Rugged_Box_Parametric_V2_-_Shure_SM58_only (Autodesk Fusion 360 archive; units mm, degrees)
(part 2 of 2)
sketch "Sketch1" plane through (0, 0, 0) normal (0, -1, 0) x axis (1, 0, 0)
  line L1 (27, -83.5799) -> (13, -83.5799)
  line L2 (30.5799, -64) -> (30.5799, -80)
  line L3 (33.2103, -64) -> (30.5799, -64)
  line L4 (33.2103, -62.8) -> (33.2103, -64)
  line L5 (30.5799, -62.8) -> (33.2103, -62.8)
  line L6 (30.5799, -32.2) -> (30.5799, -62.8)
  line L7 (33.2103, -32.2) -> (30.5799, -32.2)
  line L8 (33.2103, -31) -> (33.2103, -32.2)
  line L9 (30.5799, -31) -> (33.2103, -31)
  line L10 (30.5799, 31) -> (30.5799, -31)
  line L11 (33.2103, 31) -> (30.5799, 31)
  line L12 (33.2103, 32.2) -> (33.2103, 31)
  line L13 (30.5799, 32.2) -> (33.2103, 32.2)
  line L14 (30.5799, 62.8) -> (30.5799, 32.2)
  line L15 (33.2103, 62.8) -> (30.5799, 62.8)
  line L16 (33.2103, 64) -> (33.2103, 62.8)
  line L17 (30.5799, 64) -> (33.2103, 64)
  line L18 (30.5799, 80) -> (30.5799, 64)
  line L19 (13, 83.5799) -> (27, 83.5799)
  line L20 (13, 86.2103) -> (13, 83.5799)
  line L21 (10, 86.2103) -> (13, 86.2103)
  line L22 (10, 83.5799) -> (10, 86.2103)
  line L23 (-10, 83.5799) -> (10, 83.5799)
  line L24 (-10, 86.2103) -> (-10, 83.5799)
  line L25 (-13, 86.2103) -> (-10, 86.2103)
  line L26 (-13, 83.5799) -> (-13, 86.2103)
  line L27 (-27, 83.5799) -> (-13, 83.5799)
  line L28 (-30.5799, 48.1) -> (-30.5799, 80)
  line L29 (-33.2103, 48.1) -> (-30.5799, 48.1)
  line L30 (-33.2103, 46.9) -> (-33.2103, 48.1)
  line L31 (-30.5799, 46.9) -> (-33.2103, 46.9)
  line L32 (-30.5799, -46.9) -> (-30.5799, 46.9)
  line L33 (-33.2103, -46.9) -> (-30.5799, -46.9)
  line L34 (-33.2103, -48.1) -> (-33.2103, -46.9)
  line L35 (-30.5799, -48.1) -> (-33.2103, -48.1)
  line L36 (-30.5799, -80) -> (-30.5799, -48.1)
  line L37 (-13, -83.5799) -> (-27, -83.5799)
  line L38 (-13, -86.2103) -> (-13, -83.5799)
  line L39 (-10, -86.2103) -> (-13, -86.2103)
  line L40 (-10, -83.5799) -> (-10, -86.2103)
  line L41 (10, -83.5799) -> (-10, -83.5799)
  line L42 (10, -86.2103) -> (10, -83.5799)
  line L43 (13, -86.2103) -> (10, -86.2103)
  line L44 (13, -83.5799) -> (13, -86.2103)
  curve K1
  curve K2
  curve K3
  curve K4
  curve K5
  curve K6
  curve K7
  curve K8
  line L45 (-21.211, -1.1301) -> (-5.3045, -3.1151)
  curve K9 (-19.3176, 40.6782) -> (-15.6607, 42.0595)
  curve K10 (2.8159, -3.752) -> (1.8168, -8.457)
  line L46 (-16.007, 15.7968) -> (-21.211, 16.4496)
  curve K11 (-9.0516, -67.3301) -> (-19.8563, -68.0148)
  line L47 (1.8234, 23.3639) -> (1.8234, 13.6154)
  line L48 (-21.211, 16.4496) -> (-21.211, 36.7321)
  line L49 (1.8247, -33.0691) -> (1.8247, -44.2373)
  line L50 (-13.1967, 31.4711) -> (-16.007, 31.8545)
  curve K12 (-9.8039, -47.4736) -> (-9.1657, -46.5952)
  line L51 (-10.21, -13.8959) -> (-21.211, -12.5106)
  line L52 (-19.8563, -68.0015) -> (-19.8656, -67.9511)
  line L53 (-5.3045, -3.1151) -> (-5.3045, -0.107)
  curve K13 (-4.1276, -13.7313) -> (-10.21, -13.8959)
  line L54 (-21.211, 13.3965) -> (-9.7695, 12.0033)
  line L55 (-13.2392, -31.1969) -> (-13.2392, -27.7444)
  line L56 (-5.3045, -0.107) -> (-21.211, 1.8488)
  line L57 (1.8287, 67.7994) -> (1.8287, 43.0268)
  line L58 (-21.2123, -15.581) -> (1.8247, -18.4099)
  line L59 (2.8159, -2.6905) -> (2.8159, -3.752)
  line L60 (1.8168, -8.457) -> (1.5925, -8.8697)
  curve K14 (-19.8656, -67.9511) -> (-21.215, -64.0793)
  line L61 (-4.0294, 43.7313) -> (-21.2163, 45.8424)
  line L62 (-21.211, 13.3965) -> (-21.211, 1.8488)
  line L63 (-21.211, -12.5106) -> (-21.211, -1.1301)
  line L64 (-6.2506, -28.64) -> (-6.2506, -32.0779)
  curve K15 (-21.211, 36.7321) -> (-19.3176, 40.6782)
  curve K16 (-5.2236, 10.6844) -> (1.1971, 4.4255)
  line L65 (1.8234, 13.6154) -> (-13.1967, 15.4637)
  curve K17 (-9.1657, -46.5952) -> (-3.3341, -45.7234)
  line L66 (1.8327, -53.2109) -> (1.8407, -72.6495)
  line L67 (-13.1967, 15.4637) -> (-13.1967, 31.4711)
  line L68 (-21.2123, -26.7466) -> (-21.2123, -15.581)
  line L69 (-21.2163, 45.8424) -> (-21.2163, 70.6269)
  line L70 (-19.8563, -68.0148) -> (-19.8656, -68.0148)
  line L71 (-8.351, 35.2526) -> (-4.0294, 43.7313)
  curve K18 (-3.3341, -45.7234) -> (-1.2828, -46.8022)
  curve K19 (-9.9101, 38.8723) -> (-8.351, 35.2526)
  line L72 (1.8247, -18.4099) -> (1.8247, -29.5741)
  curve K20 (1.1971, 4.4255) -> (1.2449, 4.3114)
  line L73 (-4.4195, -71.88) -> (-4.4222, -56.0518)
  line L74 (-6.2506, -32.0779) -> (1.8247, -33.0691)
  line L75 (1.8287, 43.0268) -> (5.2427, 42.6207)
  line L76 (1.8247, -29.5741) -> (-6.2864, -28.5763)
  line L77 (-21.2123, -41.4231) -> (-21.2123, -30.2561)
  curve K21 (-1.2828, -46.8022) -> (1.8327, -53.2109)
  curve K22 (-19.8656, -68.0148) -> (-19.8563, -68.0015)
  line L78 (-13.1702, 69.6411) -> (-7.2975, 68.9219)
  line L79 (5.2427, 42.6207) -> (-5.8034, 24.3126)
  line L80 (1.8407, -72.6495) -> (-4.4195, -71.88)
  line L81 (-7.2975, 68.9219) -> (-7.2975, 55.4436)
  line L82 (1.8247, -44.2373) -> (-21.2123, -41.4231)
  line L83 (-5.8034, 24.3126) -> (1.8234, 23.3639)
  line L84 (-4.243, 55.027) -> (-4.2324, 68.5411)
  curve K23 (1.2449, 4.3114) -> (2.8159, -2.6905)
  line L85 (-15.9261, 56.6258) -> (-13.1596, 56.2477)
  curve K24 (1.5925, -8.8697) -> (-4.1276, -13.7313)
  line L86 (-7.2975, 55.4436) -> (-4.243, 55.027)
  line L87 (-15.9261, 69.9781) -> (-15.9261, 56.6258)
  curve K25 (-10.2683, -48.2883) -> (-9.8039, -47.4736)
  curve K26 (-12.2056, 41.0192) -> (-9.9101, 38.8723)
  line L88 (-4.2324, 68.5411) -> (1.8287, 67.7994)
  line L89 (-21.2123, -30.2561) -> (-13.2299, -31.2287)
  line L90 (-13.1596, 56.2477) -> (-13.1702, 69.6411)
  curve K27 (-9.7695, 12.0033) -> (-5.2236, 10.6844)
  line L91 (-13.2299, -27.7245) -> (-21.2123, -26.7466)
  curve K28 (-20.2119, 75.4196) -> (-19.7952, 76.0472)
  line L92 (-6.2864, -28.5763) -> (-6.2506, -28.64)
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  point P55 (-21.211, 1.8488)
  point P164 (-21.211, 1.8488)
  point P70 (-21.211, 13.3965)
  point P165 (-21.211, 13.3965)
  coincident P55 P164
  coincident P70 P165
  dimension "d197" Text1-Height = 10
  dimension "d199" Text2-Height = 10
  dimension "d200" 58 = "'58'"
extrude "Extrude1" new body sketch "Sketch1" along a picked direction blind -2 (= "-WallThickness + 0.4 mm")
combine "Combine1"
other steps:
base_feature "Base Feature1" bodies "Box - Lid"
base_feature "Base Feature1" bodies "Box Waterproof", "Box - Bottom"
base_feature "Base Feature1" bodies "Latch", "Box - Latch"
create_component "CreateComponent1"
remove_body "RemoveBody1"
create_component "CreateComponent3"
remove_body "RemoveBody3"
create_component "CreateComponent1"
create_component "CreateComponent1"
remove_body "RemoveBody1"
create_component "CreateComponent2"
joint_origin "JointOrigin2"
joint_origin "JointOrigin2"
create_component "CreateComponent3"
joint_origin "JointOrigin2"
joint_origin "JointOrigin4"
create_component "CreateComponent4"
named bodies: "Box Waterproof", "Latch", "Box - Latch", "Box - Bottom", "Box - Lid", "Box - Seal", "Box - Latch (1)", "Lid divider", "Box divider"

design "Shure SM58"
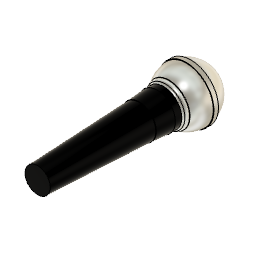
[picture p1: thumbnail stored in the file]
sketch "Sketch1" plane through (0, 0, 0) normal (0, 1, 0) x axis (1, 0, 0)
  circle C1 centre (0, 0) radius 11.7
  circle C2 centre (0, 0) radius 15.6
  circle C3 centre (0, 0) radius 15.75
  circle C4 centre (0, 0) radius 16.875
  circle C5 centre (0, 0) radius 16.75
  circle C6 centre (0, 0) radius 19.3
  circle C7 centre (0, 0) radius 25.5
  circle C8 centre (0, 0) radius 24.9
  circle C9 centre (0, 0) radius 8
  point P1 (0, 0)
  point P2 (0, 0)
  point P3 (0, 0)
  point P4 (0, 0)
  coincident P1 P2
  coincident P1 P3
  coincident P1 P4
  concentric C1 C4
  concentric C2 C5
  concentric C2 C6
  concentric C4 C7
  concentric C4 C8
  concentric C5 C9
  dimension "d1" diameter C1 = 23.4
  dimension "d2" diameter C2 = 31.2
  dimension "d3" diameter C3 = 31.5
  dimension "d4" diameter C4 = 33.75
  dimension "d5" diameter C5 = 33.5
  dimension "d17" diameter C6 = 38.6
  dimension "d26" diameter C7 = 51
  dimension "d27" diameter C8 = 49.8
  dimension "d36" diameter C9 = 16
  dimension "d41" ProfileOffset = 1
  dimension "d42" AlongDistance = 2
  dimension "d43" TaperAngle = 0
work_plane "WorkPlane1" sketch "Sketch1" AlongDistance 93.5
sketch "Sketch2" plane through (0, 93.5, 0) normal (0, 1, 0) x axis (1, 0, 0)
  circle C1 centre (0, 0) radius 15.6
  circle C2 centre (0, 0) radius 15.75
loft "Loft1" sketch "Sketch1" + "Sketch2"
fillet "Fillet1" radius 0.25
work_plane "WorkPlane3" AlongDistance 16.5
sketch "Sketch4" plane through (0, 110, 0) normal (0, 1, 0) x axis (1, 0, 0)
  circle C1 centre (0, 0) radius 16.875
  circle C2 centre (0, 0) radius 16.75
loft "Loft2" sketch "Sketch2" + "Sketch4"
fillet "Fillet2" radius 0.25
combine "Combine1"
extrude "Extrude1" add sketch "Sketch4" profile of C2 along normal blind 6
fillet "Fillet3" radius 0.1
work_plane "WorkPlane5" AlongDistance 5
sketch "Sketch6" plane through (0, 121, 0) normal (0, 1, 0) x axis (1, 0, 0)
  circle C1 centre (0, 0) radius 16.75
  circle C2 centre (0, 0) radius 19.3
extrude "Extrude2" new body of existing geometry blind 2.5
extrude "Extrude3" add sketch "Sketch6" against normal blind 2.5
fillet "Fillet4" radius 5
work_plane "WorkPlane6" AlongDistance 20.9 (= "49.8 mm / 2 - 4 mm")
sketch "Sketch7" plane through (0, 136.9, 0) normal (0, 1, 0) x axis (1, 0, 0)
  line L1 (0, 25.5) -> (0, -25.5)
  circle C1 centre (0, 0) radius 25.5
  circle C2 centre (0, 0) radius 24.9
  circle C3 centre (0, 0) radius 23.9
  circle C4 centre (0, 0) radius 25.3
  point P4 (0, -25.5)
  point P5 (0, 25.5)
  coincident C1 P4
  coincident C1 P5
  vertical L1
  dimension "d39" = -1
  dimension "d40" = -0.2
sphere_primitive "SpherePrimitive1" Diameter 49.8
fillet "Fillet6" radius 4
extrude "Extrude4" add sketch "Sketch7" profile of C1 C2 C3 along normal blind 4.15
work_plane "WorkPlane7" AlongDistance 166.5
